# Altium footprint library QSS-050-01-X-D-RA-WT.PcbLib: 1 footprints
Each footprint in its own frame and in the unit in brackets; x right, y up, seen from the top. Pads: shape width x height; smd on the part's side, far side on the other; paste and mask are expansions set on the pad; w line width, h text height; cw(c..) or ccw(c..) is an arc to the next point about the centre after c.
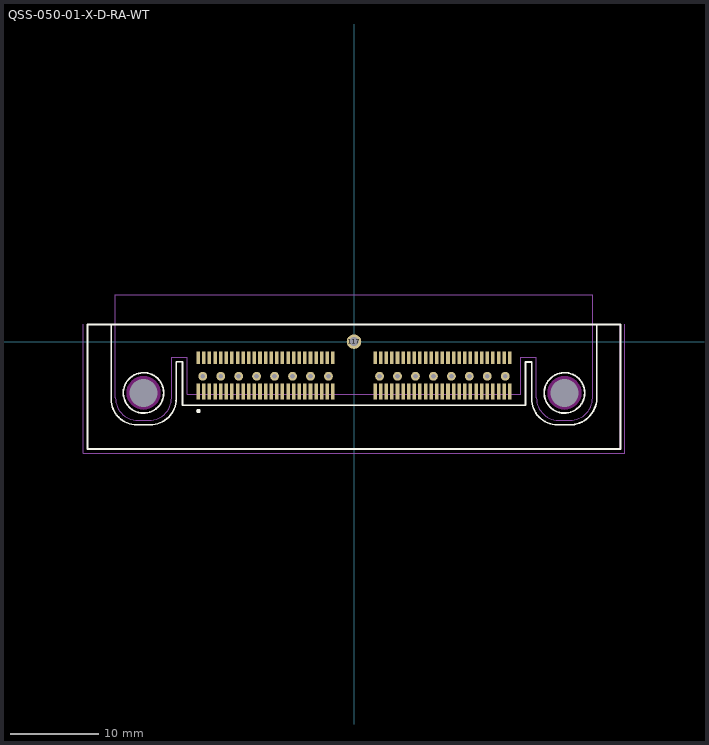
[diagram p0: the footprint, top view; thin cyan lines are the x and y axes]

## QSS-050-01-X-D-RA-WT [mm] "0.635mm pitch, 100 pin, high speed socket strip; r/a"
height 8.33
pads (119):
  rect 0.4x1.8 smd mask+0: 1(-17.621,-5.652) 3(-16.986,-5.652) 5(-16.351,-5.652) 7(-15.716,-5.652) 9(-15.081,-5.652) 11(-14.446,-5.652) 13(-13.811,-5.652) 15(-13.176,-5.652) 17(-12.541,-5.652) 19(-11.906,-5.652) 21(-11.271,-5.652) 23(-10.636,-5.652) 25(-10.001,-5.652) 27(-9.366,-5.652) 29(-8.731,-5.652) 31(-8.096,-5.652) 33(-7.461,-5.652) 35(-6.826,-5.652) 37(-6.191,-5.652) 39(-5.556,-5.652) 41(-4.921,-5.652) 43(-4.286,-5.652) 45(-3.651,-5.652) 47(-3.016,-5.652) 49(-2.381,-5.652) 51(2.382,-5.652) 53(3.017,-5.652) 55(3.652,-5.652) 57(4.287,-5.652) 59(4.922,-5.652) 61(5.557,-5.652) 63(6.192,-5.652) 65(6.827,-5.652) 67(7.462,-5.652) 69(8.097,-5.652) 71(8.732,-5.652) 73(9.367,-5.652) 75(10.002,-5.652) 77(10.637,-5.652) 79(11.272,-5.652) 81(11.907,-5.652) 83(12.542,-5.652) 85(13.177,-5.652) 87(13.812,-5.652) 89(14.447,-5.652) 91(15.082,-5.652) 93(15.717,-5.652) 95(16.352,-5.652) 97(16.987,-5.652) 99(17.622,-5.652)
  rect 0.4x1.4 smd mask+0: 2(-17.621,-1.842) 4(-16.986,-1.842) 6(-16.351,-1.842) 8(-15.716,-1.842) 10(-15.081,-1.842) 12(-14.446,-1.842) 14(-13.811,-1.842) 16(-13.176,-1.842) 18(-12.541,-1.842) 20(-11.906,-1.842) 22(-11.271,-1.842) 24(-10.636,-1.842) 26(-10.001,-1.842) 28(-9.366,-1.842) 30(-8.731,-1.842) 32(-8.096,-1.842) 34(-7.461,-1.842) 36(-6.826,-1.842) 38(-6.191,-1.842) 40(-5.556,-1.842) 42(-4.921,-1.842) 44(-4.286,-1.842) 46(-3.651,-1.842) 48(-3.016,-1.842) 50(-2.381,-1.842) 52(2.382,-1.842) 54(3.017,-1.842) 56(3.652,-1.842) 58(4.287,-1.842) 60(4.922,-1.842) 62(5.557,-1.842) 64(6.192,-1.842) 66(6.827,-1.842) 68(7.462,-1.842) 70(8.097,-1.842) 72(8.732,-1.842) 74(9.367,-1.842) 76(10.002,-1.842) 78(10.637,-1.842) 80(11.272,-1.842) 82(11.907,-1.842) 84(12.542,-1.842) 86(13.177,-1.842) 88(13.812,-1.842) 90(14.447,-1.842) 92(15.082,-1.842) 94(15.717,-1.842) 96(16.352,-1.842) 98(16.987,-1.842) 100(17.622,-1.842)
  round 1 hole 0.55 mask+0: 101(-17.113,-3.925) 102(-15.081,-3.925) 103(-13.049,-3.925) 104(-11.017,-3.925) 105(-8.985,-3.925) 106(-6.953,-3.925) 107(-4.921,-3.925) 108(-2.889,-3.925) 109(2.89,-3.925) 110(4.922,-3.925) 111(6.954,-3.925) 112(8.986,-3.925) 113(11.018,-3.925) 114(13.05,-3.925) 115(15.082,-3.925) 116(17.114,-3.925)
  round 1.65 hole 1 mask+0: 117(0,0)
  round 1 hole 3.2 unplated mask+0: 118(-23.813,-5.804) 119(23.813,-5.804)
Top Overlay:
  circle w0.25: c-17.6,-7.85 r0.125
  circle w0.2: c23.813,-5.804 r2.286
  circle w0.2: c-23.813,-5.804 r2.286
  lines w0.2: 20.11,-6.469 ccw(c23.022,-6.499) 22.992,-9.411 ; 20.111,-6.467 20.111,-2.299 19.399,-2.299 19.399,-7.201 -19.399,-7.201 -19.399,-2.274 -20.111,-2.274 -20.111,-6.465 cw(c-23.057,-6.465) -23.057,-9.411 -24.594,-9.411 cw(c-24.594,-6.528) -27.477,-6.528 -27.477,1.95 27.477,1.95 27.477,-6.423 cw(c24.418,-6.353) 24.349,-9.411 22.991,-9.411 ; -30.15,-12.15 -30.15,1.95 30.15,1.95 30.15,-12.15 -30.15,-12.15
Keep-Out Layer:
  pour cut-out: 25.722,-5.804 25.686,-5.432 25.577,-5.073 25.4,-4.743 25.163,-4.454 24.874,-4.217 24.544,-4.04 24.185,-3.931 23.813,-3.895 23.441,-3.931 23.082,-4.04 22.752,-4.217 22.463,-4.454 22.226,-4.743 22.049,-5.073 21.94,-5.432 21.904,-5.804 21.94,-6.176 22.049,-6.535 22.226,-6.865 22.463,-7.154 22.752,-7.391 23.082,-7.568 23.441,-7.677 23.813,-7.713 24.185,-7.677 24.544,-7.568 24.874,-7.391 25.163,-7.154 25.4,-6.865 25.577,-6.535 25.686,-6.176
  pour cut-out: -21.904,-5.804 -21.94,-5.432 -22.049,-5.073 -22.226,-4.743 -22.463,-4.454 -22.752,-4.217 -23.082,-4.04 -23.441,-3.931 -23.813,-3.895 -24.185,-3.931 -24.544,-4.04 -24.874,-4.217 -25.163,-4.454 -25.4,-4.743 -25.577,-5.073 -25.686,-5.432 -25.722,-5.804 -25.686,-6.176 -25.577,-6.535 -25.4,-6.865 -25.163,-7.154 -24.874,-7.391 -24.544,-7.568 -24.185,-7.677 -23.813,-7.713 -23.441,-7.677 -23.082,-7.568 -22.752,-7.391 -22.463,-7.154 -22.226,-6.865 -22.049,-6.535 -21.94,-6.176
Mechanical 12:
  lines w0.001: -30.15,-12.15 -30.15,1.95 30.15,1.95 30.15,-12.15 -30.15,-12.15
Mechanical 13:
  lines w0.1: 20.638,-6.365 ccw(c23.158,-6.382) 23.141,-8.903 ; 20.638,-6.363 20.638,-1.791 18.891,-1.791 18.891,-5.982 -18.891,-5.982 -18.891,-1.791 -20.638,-1.791 -20.638,-6.363 cw(c-23.178,-6.363) -23.178,-8.903 -24.448,-8.903 cw(c-24.448,-6.363) -26.988,-6.363 -26.988,5.321 26.988,5.321 26.988,-6.363 cw(c24.447,-6.363) 24.407,-8.903 ; 23.139,-8.903 24.409,-8.903
  text ".Designator" at 0,0 h1.52
Mechanical 15:
  lines w0.05: -30.65,1.95 -30.65,-12.65 30.65,-12.65 30.65,1.95 ; -0.5,0 0.5,0 ; 0,-0.5 0,0.5
Drill Drawing:
  lines w0.01: -36,2.451 36,2.451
